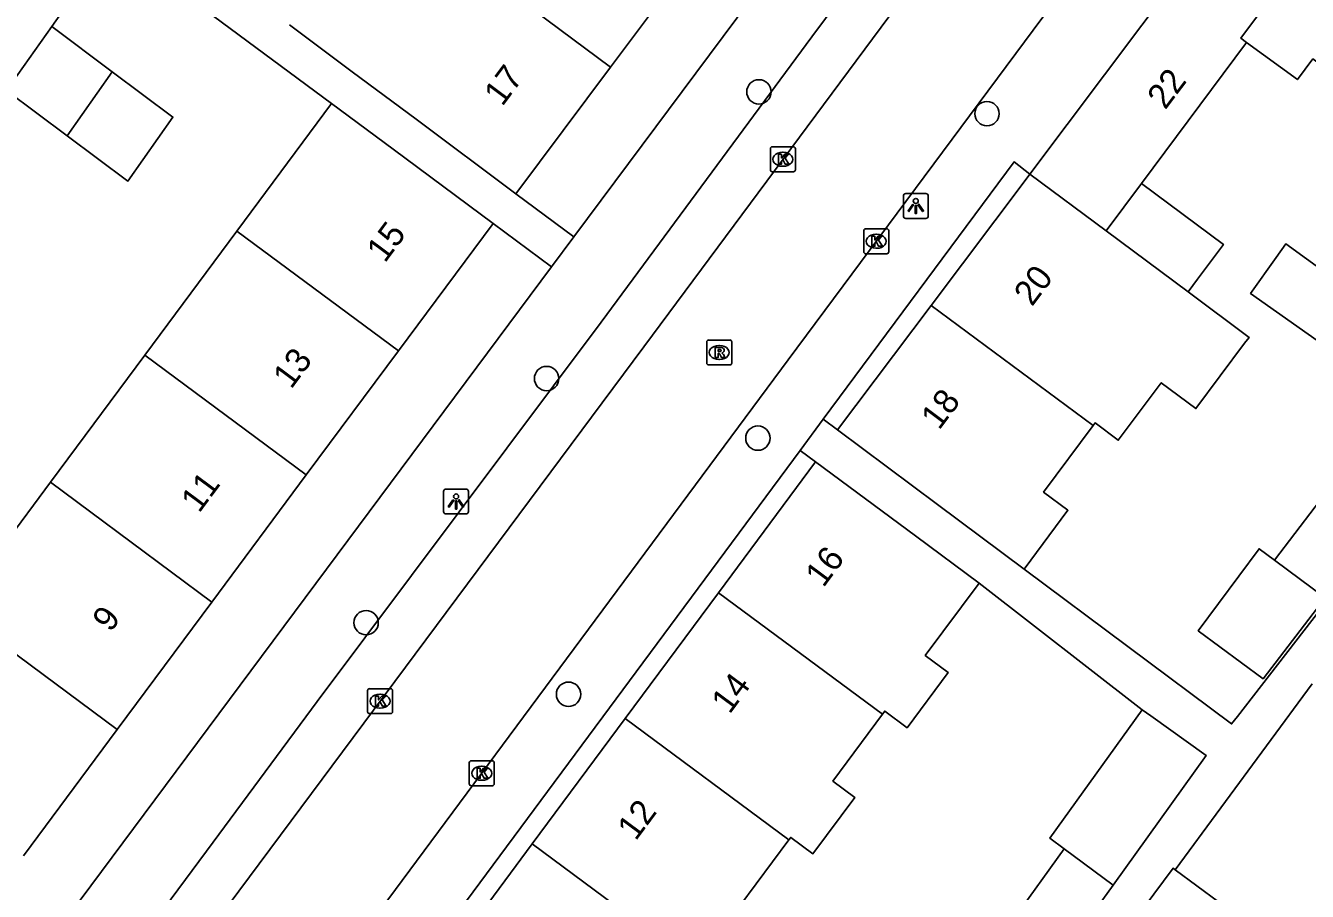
# Model space of a CAD drawing. Extents: x 160026 to 161302, y 384757 to 385701.
# Drawn here: x 160300.1 to 160351.5, y 385210 to 385244.8 of the extents above; entities that cross this region are included whole.
import ezdxf

# ---------------------------------------------------------------- set-up
doc = ezdxf.new("R2010")
doc.units = 0
for name, color, linetype in [('IMGEO_Boom', 7, 'Continuous'), ('IMGEO_Kolk', 7, 'Continuous'), ('IMGEO_Lichtpunt', 7, 'Continuous'), ('IMGEO_Pand', 7, 'Continuous'), ('IMGEO_Pand_nummerreeks', 7, 'Continuous'), ('IMGEO_Rijbaan_lokaal_open', 7, 'Continuous'), ('IMGEO_Rioolput', 7, 'Continuous'), ('IMGEO_Voetpad_open', 7, 'Continuous')]:
    doc.layers.add(name, color=color, linetype=linetype)

msp = doc.modelspace()

# ---------------------------------------------------------------- linework, layer by layer
at = {"layer": 'IMGEO_Boom'}
for centre in [(160329.488, 385242.097), (160338.638, 385241.221), (160320.969, 385230.593), (160329.447, 385228.201), (160313.73, 385220.796), (160321.85, 385217.924)]:
    msp.add_circle(centre, 0.489, dxfattribs=at)
at = {"layer": 'IMGEO_Kolk'}
for p, q in [((160329.949, 385238.965), (160329.949, 385239.817)), ((160330.024, 385239.891), (160330.876, 385239.891)), ((160330.437, 385239.671), (160330.462, 385239.671)), ((160330.95, 385239.817), (160330.95, 385238.965)), ((160330.46, 385239.111), (160330.435, 385239.111)), ((160330.876, 385238.891), (160330.024, 385238.891)), ((160333.695, 385235.675), (160333.695, 385236.527)), ((160333.77, 385236.601), (160334.622, 385236.601)), ((160334.183, 385236.381), (160334.208, 385236.381)), ((160334.696, 385236.527), (160334.696, 385235.675)), ((160334.622, 385235.601), (160333.77, 385235.601)), ((160334.206, 385235.821), (160334.181, 385235.821)), ((160313.787, 385217.222), (160313.787, 385218.074)), ((160313.862, 385218.148), (160314.714, 385218.148)), ((160314.275, 385217.928), (160314.3, 385217.928)), ((160314.788, 385218.074), (160314.788, 385217.222)), ((160314.298, 385217.368), (160314.273, 385217.368)), ((160314.714, 385217.148), (160313.862, 385217.148)), ((160317.867, 385214.326), (160317.867, 385215.178)), ((160317.942, 385215.252), (160318.794, 385215.252)), ((160318.355, 385215.032), (160318.38, 385215.032)), ((160318.868, 385215.178), (160318.868, 385214.326)), ((160318.794, 385214.252), (160317.942, 385214.252)), ((160318.378, 385214.472), (160318.353, 385214.472))]:
    msp.add_line(p, q, dxfattribs=at)
for points in [[(160329.949, 385238.965), (160329.949, 385239.817)], [(160330.024, 385239.891), (160330.876, 385239.891)], [(160330.27, 385239.591), (160330.393, 385239.591), (160330.393, 385239.44), (160330.523, 385239.591), (160330.687, 385239.591), (160330.541, 385239.44), (160330.694, 385239.191), (160330.542, 385239.191), (160330.457, 385239.355), (160330.393, 385239.288), (160330.393, 385239.191), (160330.27, 385239.191), (160330.27, 385239.591)], [(160330.95, 385239.817), (160330.95, 385238.965)], [(160330.876, 385238.891), (160330.024, 385238.891)], [(160333.695, 385235.675), (160333.695, 385236.527)], [(160333.77, 385236.601), (160334.622, 385236.601)], [(160334.696, 385236.527), (160334.696, 385235.675)], [(160334.016, 385236.301), (160334.139, 385236.301), (160334.139, 385236.15), (160334.269, 385236.301), (160334.433, 385236.301), (160334.287, 385236.15), (160334.44, 385235.901), (160334.288, 385235.901), (160334.203, 385236.065), (160334.139, 385235.998), (160334.139, 385235.901), (160334.016, 385235.901), (160334.016, 385236.301)], [(160334.622, 385235.601), (160333.77, 385235.601)], [(160313.787, 385217.222), (160313.787, 385218.074)], [(160313.862, 385218.148), (160314.714, 385218.148)], [(160314.108, 385217.848), (160314.231, 385217.848), (160314.231, 385217.697), (160314.361, 385217.848), (160314.525, 385217.848), (160314.379, 385217.697), (160314.532, 385217.448), (160314.38, 385217.448), (160314.295, 385217.612), (160314.231, 385217.545), (160314.231, 385217.448), (160314.108, 385217.448), (160314.108, 385217.848)], [(160314.788, 385218.074), (160314.788, 385217.222)], [(160314.714, 385217.148), (160313.862, 385217.148)], [(160317.867, 385214.326), (160317.867, 385215.178)], [(160317.942, 385215.252), (160318.794, 385215.252)], [(160318.188, 385214.952), (160318.311, 385214.952), (160318.311, 385214.801), (160318.441, 385214.952), (160318.605, 385214.952), (160318.459, 385214.801), (160318.612, 385214.552), (160318.46, 385214.552), (160318.375, 385214.716), (160318.311, 385214.649), (160318.311, 385214.552), (160318.188, 385214.552), (160318.188, 385214.952)], [(160318.868, 385215.178), (160318.868, 385214.326)], [(160318.794, 385214.252), (160317.942, 385214.252)]]:
    msp.add_lwpolyline(points, dxfattribs=at)
for centre, start, end in [((160330.026, 385239.815), 91.552, 178.448), ((160330.026, 385239.815), 91.552, 178.448), ((160330.874, 385239.815), 1.552, 88.448), ((160330.874, 385239.815), 1.552, 88.448), ((160330.026, 385238.967), 181.552, 268.448), ((160330.026, 385238.967), 181.552, 268.448), ((160330.874, 385238.967), 271.552, 358.448), ((160330.874, 385238.967), 271.552, 358.448), ((160333.772, 385236.525), 91.552, 178.448), ((160333.772, 385236.525), 91.552, 178.448), ((160334.62, 385236.525), 1.552, 88.448), ((160334.62, 385236.525), 1.552, 88.448), ((160333.772, 385235.677), 181.552, 268.448), ((160333.772, 385235.677), 181.552, 268.448), ((160334.62, 385235.677), 271.552, 358.448), ((160334.62, 385235.677), 271.552, 358.448), ((160313.864, 385218.072), 91.552, 178.448), ((160313.864, 385218.072), 91.552, 178.448), ((160314.712, 385218.072), 1.552, 88.448), ((160314.712, 385218.072), 1.552, 88.448), ((160313.864, 385217.224), 181.552, 268.448), ((160313.864, 385217.224), 181.552, 268.448), ((160314.712, 385217.224), 271.552, 358.448), ((160314.712, 385217.224), 271.552, 358.448), ((160317.944, 385215.176), 91.552, 178.448), ((160317.944, 385215.176), 91.552, 178.448), ((160318.792, 385215.176), 1.552, 88.448), ((160318.792, 385215.176), 1.552, 88.448), ((160317.944, 385214.328), 181.552, 268.448), ((160317.944, 385214.328), 181.552, 268.448), ((160318.792, 385214.328), 271.552, 358.448), ((160318.792, 385214.328), 271.552, 358.448)]:
    msp.add_arc(centre, 0.0765, start, end, dxfattribs=at)
for centre, major_axis, ratio, start_param, end_param in [((160330.436, 385239.391), (-0.387, 0.002), 0.722429, 4.712389, 7.853982), ((160330.461, 385239.391), (-0.39, 0.002), 0.717154, 1.570796, 4.712389), ((160334.182, 385236.101), (-0.387, 0.002), 0.722429, 4.712389, 7.853982), ((160334.207, 385236.101), (-0.39, 0.002), 0.717154, 1.570796, 4.712389), ((160314.274, 385217.648), (-0.387, 0.002), 0.722429, 4.712389, 7.853982), ((160314.299, 385217.648), (-0.39, 0.002), 0.717154, 1.570796, 4.712389), ((160318.354, 385214.752), (-0.387, 0.002), 0.722429, 4.712389, 7.853982), ((160318.379, 385214.752), (-0.39, 0.002), 0.717154, 1.570796, 4.712389)]:
    msp.add_ellipse(centre, major_axis=major_axis, ratio=ratio, start_param=start_param, end_param=end_param, dxfattribs=at)
at = {"layer": 'IMGEO_Lichtpunt'}
for p, q in [((160335.283, 385237.921), (160335.283, 385237.114)), ((160335.283, 385237.921), (160335.283, 385237.114)), ((160336.185, 385238.016), (160335.377, 385238.016)), ((160336.185, 385238.016), (160335.377, 385238.016)), ((160336.279, 385237.114), (160336.279, 385237.921)), ((160336.279, 385237.114), (160336.279, 385237.921)), ((160335.377, 385237.02), (160336.185, 385237.02)), ((160335.377, 385237.02), (160336.185, 385237.02)), ((160316.84, 385226.063), (160316.84, 385225.256)), ((160316.84, 385226.063), (160316.84, 385225.256)), ((160317.742, 385226.158), (160316.934, 385226.158)), ((160317.742, 385226.158), (160316.934, 385226.158)), ((160317.836, 385225.256), (160317.836, 385226.063)), ((160317.836, 385225.256), (160317.836, 385226.063)), ((160316.934, 385225.162), (160317.742, 385225.162)), ((160316.934, 385225.162), (160317.742, 385225.162))]:
    msp.add_line(p, q, dxfattribs=at)
for points in [[(160335.657, 385237.585), (160335.696, 385237.557), (160335.508, 385237.295), (160335.47, 385237.322), (160335.657, 385237.585)], [(160335.759, 385237.537), (160335.806, 385237.537), (160335.806, 385237.215), (160335.759, 385237.215), (160335.759, 385237.537)], [(160335.869, 385237.557), (160335.907, 385237.584), (160336.094, 385237.322), (160336.055, 385237.294), (160335.869, 385237.557)], [(160317.214, 385225.727), (160317.253, 385225.699), (160317.065, 385225.437), (160317.027, 385225.464), (160317.214, 385225.727)], [(160317.316, 385225.679), (160317.363, 385225.679), (160317.363, 385225.357), (160317.316, 385225.357), (160317.316, 385225.679)], [(160317.426, 385225.699), (160317.464, 385225.726), (160317.651, 385225.464), (160317.612, 385225.436), (160317.426, 385225.699)]]:
    msp.add_lwpolyline(points, dxfattribs=at)
for centre in [(160335.782, 385237.719), (160317.339, 385225.861)]:
    msp.add_circle(centre, 0.0994, dxfattribs=at)
for centre, start, end in [((160335.377, 385237.921), 90, 180), ((160335.377, 385237.921), 90, 180), ((160336.185, 385237.921), 0, 90), ((160336.185, 385237.921), 0, 90), ((160335.377, 385237.114), 180, 270), ((160335.377, 385237.114), 180, 270), ((160336.185, 385237.114), 270, 0), ((160336.185, 385237.114), 270, 360), ((160316.934, 385226.063), 90, 180), ((160316.934, 385226.063), 90, 180), ((160317.742, 385226.063), 0, 90), ((160317.742, 385226.063), 0, 90), ((160316.934, 385225.256), 180, 270), ((160316.934, 385225.256), 180, 270), ((160317.742, 385225.256), 270, 0), ((160317.742, 385225.256), 270, 360)]:
    msp.add_arc(centre, 0.0946, start, end, dxfattribs=at)
at = {"layer": 'IMGEO_Pand'}
for points in [[(160350.494, 385246.499), (160347.915, 385248.423), (160348.06, 385248.616), (160347.851, 385248.772), (160340.358, 385238.798)], [(160327.383, 385248.236), (160323.536, 385243.087)], [(160323.536, 385243.087), (160316.973, 385247.989)], [(160350.494, 385246.499), (160348.818, 385244.252), (160349.055, 385244.075)], [(160301.114, 385244.72), (160299.305, 385242.153)], [(160303.547, 385242.903), (160301.114, 385244.72)], [(160310.652, 385244.789), (160313.175, 385242.905), (160315.732, 385240.995), (160319.738, 385238.003)], [(160349.055, 385244.075), (160344.839, 385238.425)], [(160354.534, 385241.314), (160351.715, 385243.417), (160351.096, 385242.587), (160349.055, 385244.075)], [(160323.536, 385243.087), (160319.738, 385238.003)], [(160303.547, 385242.903), (160301.738, 385240.336)], [(160301.738, 385240.336), (160304.171, 385238.519), (160305.979, 385241.087), (160303.547, 385242.903)], [(160299.305, 385242.153), (160301.738, 385240.336)], [(160312.345, 385241.629), (160308.547, 385236.513)], [(160318.822, 385236.82), (160314.808, 385239.801), (160312.345, 385241.629)], [(160336.399, 385233.528), (160340.207, 385238.598), (160340.358, 385238.798)], [(160343.42, 385236.522), (160340.358, 385238.798)], [(160344.839, 385238.425), (160343.42, 385236.522)], [(160344.839, 385238.425), (160348.126, 385235.973), (160347.086, 385234.579), (160346.706, 385234.07)], [(160308.547, 385236.513), (160304.851, 385231.534)], [(160315.024, 385231.705), (160308.547, 385236.513)], [(160318.822, 385236.82), (160315.024, 385231.705)], [(160343.42, 385236.522), (160346.706, 385234.07)], [(160352.566, 385231.639), (160349.217, 385234.008), (160350.234, 385235.447), (160350.63, 385236.005), (160353.95, 385233.596), (160352.566, 385231.639)], [(160346.706, 385234.07), (160349.152, 385232.245), (160348.976, 385232.009), (160347.021, 385229.389), (160345.631, 385230.426), (160343.907, 385228.115), (160342.976, 385228.81), (160342.898, 385228.705)], [(160332.644, 385228.53), (160336.399, 385233.528)], [(160342.898, 385228.705), (160336.399, 385233.528)], [(160304.851, 385231.534), (160301.06, 385226.428)], [(160304.851, 385231.534), (160311.328, 385226.726)], [(160315.024, 385231.705), (160311.328, 385226.726)], [(160342.898, 385228.705), (160340.908, 385226.038), (160341.886, 385225.308), (160340.125, 385222.948)], [(160340.125, 385222.948), (160336.652, 385225.54), (160332.644, 385228.53)], [(160327.865, 385221.999), (160331.76, 385227.256)], [(160331.76, 385227.256), (160335.776, 385224.276), (160338.322, 385222.387)], [(160311.328, 385226.726), (160307.537, 385221.619)], [(160301.06, 385226.428), (160297.333, 385221.408)], [(160307.537, 385221.619), (160301.06, 385226.428)], [(160350.173, 385223.306), (160352.62, 385226.513), (160354.619, 385224.965), (160352.202, 385221.799)], [(160352.202, 385221.799), (160349.716, 385218.543), (160347.116, 385220.473), (160349.558, 385223.762), (160350.173, 385223.306)], [(160350.173, 385223.306), (160352.202, 385221.799)], [(160324.124, 385216.951), (160327.865, 385221.999)], [(160327.865, 385221.999), (160334.446, 385217.121)], [(160338.322, 385222.387), (160336.165, 385219.481), (160337.081, 385218.801), (160335.434, 385216.583), (160334.539, 385217.247), (160334.446, 385217.121)], [(160303.741, 385216.506), (160307.537, 385221.619)], [(160303.741, 385216.506), (160297.264, 385221.315), (160297.333, 385221.408)], [(160320.394, 385211.918), (160324.124, 385216.951)], [(160330.692, 385212.083), (160324.124, 385216.951)], [(160334.446, 385217.121), (160332.454, 385214.437), (160333.332, 385213.785), (160331.654, 385211.523), (160330.765, 385212.182), (160330.692, 385212.083)], [(160341.732, 385211.72), (160341.161, 385212.143), (160344.87, 385217.305)], [(160344.87, 385217.305), (160345.207, 385217.063), (160347.437, 385215.461), (160343.701, 385210.261)], [(160299.977, 385211.436), (160303.741, 385216.506)], [(160316.644, 385206.857), (160320.394, 385211.918)], [(160326.977, 385207.039), (160320.394, 385211.918)], [(160330.692, 385212.083), (160328.723, 385209.43), (160329.627, 385208.76), (160327.963, 385206.517), (160327.077, 385207.174), (160326.977, 385207.039)], [(160341.701, 385207.476), (160339.711, 385208.906), (160341.732, 385211.72)], [(160341.732, 385211.72), (160343.701, 385210.261)], [(160344.225, 385208.216), (160344.134, 385208.283), (160346.103, 385210.94), (160346.193, 385210.873)], [(160346.193, 385210.873), (160348.792, 385208.947)], [(160343.701, 385210.261), (160341.701, 385207.476)]]:
    msp.add_lwpolyline(points, dxfattribs=at)
at = {"layer": 'IMGEO_Rijbaan_lokaal_open'}
for points in [[(160343.367, 385256.794), (160338.325, 385250), (160324.865, 385231.862), (160302.789, 385202.19), (160297.606, 385195.246), (160297.273, 385194.799)], [(160285.665, 385171.185), (160307.17, 385199.641), (160330.662, 385231.346), (160344.518, 385250), (160349.029, 385256.073)]]:
    msp.add_lwpolyline(points, dxfattribs=at)
at = {"layer": 'IMGEO_Rioolput'}
for p, q in [((160327.396, 385231.213), (160327.396, 385232.065)), ((160327.471, 385232.139), (160328.323, 385232.139)), ((160327.884, 385231.919), (160327.909, 385231.919)), ((160328.397, 385232.065), (160328.397, 385231.213)), ((160327.907, 385231.359), (160327.882, 385231.359)), ((160328.323, 385231.139), (160327.471, 385231.139))]:
    msp.add_line(p, q, dxfattribs=at)
for points in [[(160327.396, 385231.213), (160327.396, 385232.065)], [(160327.471, 385232.139), (160328.323, 385232.139)], [(160327.985, 385231.837), (160327.733, 385231.839), (160327.733, 385231.439)], [(160327.911, 385231.758), (160327.857, 385231.758), (160327.857, 385231.677)], [(160328.397, 385232.065), (160328.397, 385231.213)], [(160327.733, 385231.439), (160327.857, 385231.439), (160327.857, 385231.601), (160327.868, 385231.601)], [(160327.857, 385231.677), (160327.909, 385231.677)], [(160327.915, 385231.572), (160327.986, 385231.439), (160328.126, 385231.439), (160328.061, 385231.565)], [(160328.323, 385231.139), (160327.471, 385231.139)]]:
    msp.add_lwpolyline(points, dxfattribs=at)
for centre, radius, start, end in [((160327.473, 385232.063), 0.0765, 91.552, 178.448), ((160327.473, 385232.063), 0.0765, 91.552, 178.448), ((160327.917, 385231.662), 0.0964, 77.0061, 93.1865), ((160327.931, 385231.719), 0.0378, 276.6634, 79.6772), ((160327.984, 385231.727), 0.109, 350.3612, 89.416), ((160327.982, 385231.727), 0.112, 277.5842, 350.9817), ((160328.321, 385232.063), 0.0765, 1.552, 88.448), ((160328.321, 385232.063), 0.0765, 1.552, 88.448), ((160327.473, 385231.215), 0.0765, 181.552, 268.448), ((160327.473, 385231.215), 0.0765, 181.552, 268.448), ((160327.867, 385231.548), 0.0533, 26.0293, 88.6989), ((160327.893, 385231.866), 0.19, 274.7715, 282.9687), ((160327.966, 385231.512), 0.108, 29.5134, 73.7905), ((160328.321, 385231.215), 0.0765, 271.552, 358.448), ((160328.321, 385231.215), 0.0765, 271.552, 358.448)]:
    msp.add_arc(centre, radius, start, end, dxfattribs=at)
for centre, major_axis, ratio, start_param, end_param in [((160327.883, 385231.639), (-0.387, 0.002), 0.722429, 4.712389, 7.853982), ((160327.908, 385231.639), (-0.39, 0.002), 0.717154, 1.570796, 4.712389)]:
    msp.add_ellipse(centre, major_axis=major_axis, ratio=ratio, start_param=start_param, end_param=end_param, dxfattribs=at)
at = {"layer": 'IMGEO_Voetpad_open'}
for points in [[(160339.449, 385254.836), (160331.618, 385244.302), (160323.154, 385232.858), (160311.767, 385217.629), (160307.587, 385211.992), (160299.736, 385201.388), (160297.814, 385198.803)], [(160301.114, 385244.72), (160303.542, 385248.163), (160312.345, 385241.629)], [(160322.058, 385236.276), (160329.154, 385245.808)], [(160340.358, 385238.798), (160339.723, 385239.288), (160332.068, 385228.956)], [(160319.738, 385238.003), (160322.058, 385236.276)], [(160321.167, 385235.078), (160318.822, 385236.82)], [(160321.167, 385235.078), (160322.058, 385236.276)], [(160291.037, 385194.602), (160321.167, 385235.078)], [(160340.125, 385222.948), (160348.455, 385216.731), (160348.689, 385217.034), (160352.316, 385221.715), (160354.9, 385225.049), (160354.239, 385228.601), (160351.887, 385230.285), (160352.872, 385231.659), (160355.928, 385229.47), (160356.185, 385227.185)], [(160332.068, 385228.956), (160331.146, 385227.711)], [(160332.644, 385228.53), (160332.068, 385228.956)], [(160331.146, 385227.711), (160301.036, 385187.071)], [(160331.146, 385227.711), (160331.76, 385227.256)], [(160344.87, 385217.305), (160338.322, 385222.387)], [(160351.681, 385218.338), (160346.193, 385210.873)]]:
    msp.add_lwpolyline(points, dxfattribs=at)

# ---------------------------------------------------------------- texts
at = {"layer": 'IMGEO_Pand_nummerreeks'}
for s, rotation, p in [('17', 53.2392, (160319.191, 385241.481)), ('22', 53.0845, (160345.792, 385241.348)), ('15', 53.409, (160314.481, 385235.2)), ('20', 53.0845, (160340.444, 385233.452)), ('13', 53.409, (160310.721, 385230.136)), ('18', 53.0839, (160336.717, 385228.492)), ('11', 53.409, (160307.029, 385225.163)), ('16', 53.4598, (160332.075, 385222.173)), ('9', 53.4111, (160303.476, 385220.377)), ('14', 53.4597, (160328.311, 385217.093)), ('12', 53.4598, (160324.544, 385212.01))]:
    msp.add_text(s, height=1, rotation=rotation, dxfattribs=at).set_placement(p)

doc.saveas('drawing.dxf')
